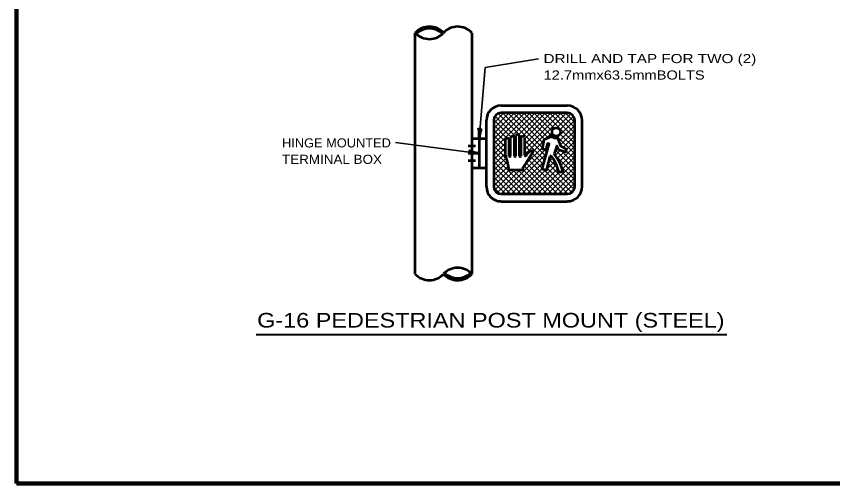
# Model space of a CAD drawing. Extents: x -370 to 486, y -203 to 341.
# Drawn here: x -312.3 to -43.9, y -191.2 to -37.7 of the extents above; entities that cross this region are included whole.
import ezdxf
from ezdxf.enums import TextEntityAlignment as Align

# ---------------------------------------------------------------- set-up
doc = ezdxf.new("R2010")
doc.units = 0
doc.header["$LTSCALE"] = 0.96
doc.header["$PDMODE"] = 32
doc.header["$PDSIZE"] = 0.48
doc.layers.add('1', color=7, linetype='Continuous', lineweight=53)

msp = doc.modelspace()

# ---------------------------------------------------------------- linework, layer by layer
at = {"layer": '1'}
for p, q in [((-181.1461, -122.3035), (-181.1461, -43.0725)), ((-162.5461, -43.0725), (-162.5461, -122.3035)), ((-152.9221, -66.98), (-131.1541, -66.98)), ((-131.1541, -69.38), (-152.9221, -69.38)), ((-157.7461, -93.572), (-157.7461, -71.804)), ((-155.3461, -71.804), (-155.3461, -93.572)), ((-128.7301, -93.572), (-128.7301, -71.804)), ((-126.3061, -93.572), (-126.3061, -71.804)), ((-149.7781, -83.636), (-149.7781, -77.396)), ((-148.6261, -77.396), (-148.6261, -83.636)), ((-148.0741, -83.636), (-148.0741, -76.82)), ((-146.9461, -76.82), (-146.9461, -83.636)), ((-146.3701, -83.636), (-146.3701, -77.396)), ((-145.2421, -77.396), (-145.2421, -83.204)), ((-161.3461, -80.288), (-163.7461, -80.288)), ((-157.7461, -77.888), (-162.5461, -77.888)), ((-160.1461, -77.888), (-160.1461, -87.488)), ((-151.4821, -83.636), (-151.4821, -77.948)), ((-150.3301, -77.948), (-150.3301, -83.636)), ((-142.4821, -82.268), (-145.3381, -86.852)), ((-161.3461, -85.088), (-163.7461, -85.088)), ((-157.7461, -87.488), (-162.5461, -87.488)), ((-132.5701, -88.844), (-133.9381, -88.844)), ((-152.9221, -95.996), (-131.1541, -95.996)), ((-152.9221, -98.42), (-131.1541, -98.42))]:
    msp.add_line(p, q, dxfattribs=at)
at = {"layer": '1', "lineweight": 25}
for p, q in [((-155.3461, -72.74), (-151.9861, -69.38)), ((-155.3461, -74.468), (-150.2581, -69.38)), ((-155.3461, -76.172), (-148.5541, -69.38)), ((-155.3461, -77.876), (-146.8501, -69.38)), ((-155.3461, -79.58), (-145.1221, -69.38)), ((-155.3461, -81.308), (-143.4181, -69.38)), ((-155.1061, -70.82), (-153.9061, -69.596)), ((-146.2501, -77.276), (-153.9301, -69.62)), ((-138.2581, -83.564), (-152.4421, -69.38)), ((-139.2661, -80.852), (-150.7381, -69.38)), ((-149.4661, -77.156), (-141.7141, -69.38)), ((-139.0021, -79.388), (-149.0101, -69.38)), ((-138.6661, -78.044), (-147.3061, -69.38)), ((-147.2101, -76.58), (-140.0101, -69.38)), ((-146.0341, -77.132), (-138.2821, -69.38)), ((-137.4421, -77.54), (-145.6021, -69.38)), ((-145.2421, -78.044), (-136.5781, -69.38)), ((-145.2421, -79.748), (-134.8741, -69.38)), ((-145.2421, -81.452), (-133.1701, -69.38)), ((-145.2421, -83.18), (-131.4421, -69.38)), ((-136.1701, -77.108), (-143.8741, -69.38)), ((-136.1701, -75.404), (-142.1701, -69.38)), ((-135.4501, -74.396), (-140.4661, -69.38)), ((-128.7301, -79.412), (-138.7621, -69.38)), ((-128.7301, -77.708), (-137.0341, -69.38)), ((-128.7301, -75.98), (-135.3301, -69.38)), ((-134.6101, -74.276), (-130.0261, -69.668)), ((-128.7301, -74.276), (-133.6261, -69.38)), ((-128.7301, -72.572), (-131.8981, -69.38)), ((-149.6821, -77.276), (-155.3221, -71.636)), ((-148.0741, -77.18), (-154.8661, -70.388)), ((-134.5381, -77.612), (-128.7301, -71.804)), ((-133.6021, -74.972), (-129.1141, -70.484)), ((-129.1621, -70.412), (-129.7381, -69.86)), ((-151.0021, -77.66), (-155.3461, -73.34)), ((-151.4821, -78.908), (-155.3461, -75.044)), ((-133.9381, -78.716), (-128.7301, -73.508)), ((-151.4821, -80.612), (-155.3461, -76.748)), ((-150.3301, -78.02), (-149.7781, -77.444)), ((-148.6261, -78.02), (-148.0741, -77.444)), ((-146.9461, -78.02), (-146.3701, -77.468)), ((-138.1861, -77.852), (-136.1701, -75.812)), ((-135.9301, -77.3), (-135.4501, -76.82)), ((-128.7301, -82.844), (-134.6101, -76.964)), ((-128.7301, -81.116), (-133.6021, -76.244)), ((-133.4821, -79.964), (-128.7301, -75.212)), ((-132.4741, -80.684), (-128.7301, -76.94)), ((-151.4821, -82.34), (-155.3461, -78.452)), ((-155.3461, -83.012), (-151.4821, -79.148)), ((-151.1941, -84.308), (-155.3461, -80.18)), ((-149.7781, -78.908), (-150.3301, -78.332)), ((-150.3301, -79.724), (-149.7781, -79.148)), ((-149.7781, -80.612), (-150.3301, -80.036)), ((-148.0741, -78.884), (-148.6261, -78.332)), ((-148.6261, -79.724), (-148.0741, -79.172)), ((-148.0741, -80.588), (-148.6261, -80.036)), ((-146.3701, -78.884), (-146.9461, -78.308)), ((-146.9461, -79.748), (-146.3701, -79.172)), ((-146.3701, -80.588), (-146.9461, -80.012)), ((-138.6181, -84.932), (-145.2421, -78.308)), ((-143.2261, -82.028), (-145.2421, -80.012)), ((-142.3861, -82.052), (-138.8581, -78.5)), ((-138.2101, -81.284), (-137.4181, -80.492)), ((-137.5381, -80.876), (-137.9701, -80.42)), ((-137.1781, -79.532), (-137.2261, -79.484)), ((-134.4181, -80.564), (-134.6101, -80.372)), ((-133.8181, -85.436), (-128.7301, -80.348)), ((-132.7141, -80.54), (-133.5781, -79.7)), ((-131.5621, -81.476), (-128.7301, -78.644)), ((-155.3461, -84.716), (-151.4821, -80.852)), ((-150.5221, -86.684), (-155.3461, -81.884)), ((-155.3461, -86.444), (-151.4821, -82.556)), ((-152.9221, -95.996), (-138.4261, -81.476)), ((-151.2181, -95.996), (-138.0661, -82.844)), ((-150.3301, -81.428), (-149.7781, -80.876)), ((-149.7781, -82.316), (-150.3301, -81.74)), ((-150.3301, -83.132), (-149.7781, -82.58)), ((-148.6261, -81.452), (-148.0741, -80.876)), ((-148.0741, -82.316), (-148.6261, -81.74)), ((-148.6261, -83.156), (-148.0741, -82.58)), ((-146.9461, -81.452), (-146.3701, -80.876)), ((-146.3701, -82.292), (-146.9461, -81.74)), ((-146.9461, -83.156), (-146.3701, -82.604)), ((-144.2101, -82.748), (-145.2421, -81.716)), ((-145.0741, -86.42), (-139.2181, -80.588)), ((-138.9781, -86.276), (-142.6741, -82.58)), ((-137.8981, -82.22), (-138.6661, -81.452)), ((-128.7301, -89.684), (-135.4741, -82.94)), ((-135.1861, -83.372), (-133.4821, -81.692)), ((-128.7301, -87.956), (-135.0661, -81.62)), ((-135.0421, -81.548), (-134.3221, -80.828)), ((-134.4421, -84.356), (-132.2341, -82.148)), ((-133.2661, -86.612), (-128.7301, -82.052)), ((-128.7301, -86.252), (-133.1701, -81.812)), ((-128.7301, -84.548), (-131.6101, -81.668)), ((-142.9381, -95.996), (-155.3461, -83.588)), ((-155.3461, -88.148), (-151.2901, -84.092)), ((-144.6421, -95.996), (-155.3461, -85.316)), ((-155.3461, -89.852), (-150.8581, -85.364)), ((-150.0661, -83.732), (-150.3301, -83.468)), ((-149.5141, -95.996), (-138.6901, -85.172)), ((-148.3621, -83.732), (-148.6261, -83.444)), ((-146.6581, -83.732), (-146.9461, -83.444)), ((-134.3701, -95.996), (-144.6421, -85.748)), ((-132.6661, -95.996), (-143.9701, -84.692)), ((-139.3381, -87.62), (-143.3221, -83.636)), ((-139.2421, -95.996), (-128.7301, -85.484)), ((-137.9941, -87.908), (-135.3061, -85.22)), ((-137.3701, -85.58), (-135.9541, -84.164)), ((-134.3221, -87.5), (-137.1301, -84.692)), ((-135.9781, -84.14), (-136.6021, -83.516)), ((-132.8341, -87.884), (-128.7301, -83.78)), ((-155.3461, -91.556), (-150.5221, -86.756)), ((-146.3461, -95.996), (-155.3461, -87.02)), ((-155.3461, -93.284), (-150.2341, -88.172)), ((-155.0581, -94.7), (-148.5061, -88.172)), ((-154.2421, -95.612), (-146.8021, -88.172)), ((-141.2101, -95.996), (-149.0581, -88.172)), ((-147.7861, -95.996), (-139.3141, -87.5)), ((-139.5061, -95.996), (-147.3541, -88.172)), ((-146.0821, -95.996), (-138.3061, -88.22)), ((-137.8021, -95.996), (-145.7941, -88.004)), ((-136.0981, -95.996), (-145.2901, -86.804)), ((-144.3781, -95.996), (-134.7541, -86.372)), ((-142.6741, -95.996), (-134.2741, -87.62)), ((-130.9861, -95.972), (-138.9781, -87.98)), ((-129.7141, -95.516), (-137.8501, -87.38)), ((-137.5381, -95.996), (-128.7301, -87.188)), ((-128.9461, -94.58), (-137.4901, -86.036)), ((-128.7301, -91.388), (-133.1221, -86.996)), ((-148.0741, -95.996), (-155.3461, -88.724)), ((-149.7781, -95.996), (-155.3461, -90.428)), ((-140.9461, -95.996), (-133.8181, -88.844)), ((-135.8101, -95.996), (-128.7301, -88.892)), ((-134.1061, -95.996), (-128.7301, -90.62)), ((-128.7301, -93.092), (-132.9781, -88.844)), ((-151.4821, -95.996), (-155.3461, -92.156)), ((-153.2101, -95.972), (-155.2981, -93.884)), ((-132.4021, -95.996), (-128.7301, -92.324)), ((-130.6261, -95.948), (-128.8021, -94.1))]:
    msp.add_line(p, q, dxfattribs=at)
at = {"layer": '1', "lineweight": 35}
msp.add_line((-160.1461, -82.688), (-187.65, -79.0884), dxfattribs=at)
at = {"layer": '1', "lineweight": 40}
msp.add_line((-233.414, -142.1299), (-78.7574, -142.1299), dxfattribs=at)
at = {"layer": '1', "lineweight": 158}
msp.add_line((479.406, -191.1602), (-312.194, -191.1602), dxfattribs=at)
msp.add_lwpolyline([(479.406, 334.9398), (-312.294, 334.8398), (-312.194, -191.1602)], dxfattribs=at)
at = {"layer": '1', "lineweight": 35}
msp.add_lwpolyline([(-160.1461, -77.888), (-158.1604, -54.4238), (-140.6305, -51.6378)], dxfattribs=at)
at = {"layer": '1'}
for points in [[(-136.8661, -83.66), (-138.0901, -88.292), (-139.3861, -87.812), (-137.1541, -79.484), (-137.7061, -79.388), (-138.2581, -81.524), (-139.3381, -81.332), (-138.7861, -78.068), (-136.2421, -77.06)], [(-134.3461, -77.588), (-133.4101, -80.156), (-131.4901, -81.26), (-131.7781, -82.316), (-134.0821, -81.476), (-134.5621, -80.18), (-135.4981, -82.772)], [(-145.7941, -87.596), (-145.7941, -88.172), (-150.3301, -88.172)]]:
    msp.add_lwpolyline(points, dxfattribs=at)
msp.add_circle((-134.8153, -75.6145), 1.3721, dxfattribs=at)
for centre, radius, start, end in [((-176.4961, -47.3865), 6.3555, 42.97503, 137.02497), ((-176.4961, -48.0533), 6.3555, 47.11243, 132.88757), ((-167.2103, -47.3865), 6.3555, 42.97503, 137.02497), ((-176.4961, -38.7401), 6.3555, 222.97503, 317.02497), ((-152.9185, -71.8067), 4.8384, 90, 180), ((-131.1457, -71.8067), 4.8384, 0, 90), ((-152.9185, -71.8067), 2.4192, 90, 180), ((-131.1457, -71.8067), 2.4192, 0, 90), ((-150.9038, -78.3176), 0.6706, 32.26726, 147.73274), ((-149.2028, -77.7506), 0.6706, 32.26726, 147.73274), ((-147.5018, -77.1836), 0.6706, 32.26726, 147.73274), ((-145.8008, -77.7506), 0.6706, 32.26726, 147.73274), ((-134.8253, -75.6562), 1.9808, 224.78621, 284.15055), ((-144.8821, -83.1081), 0.367, 196.62901, 346.9737), ((-141.8779, -84.7843), 3.0894, 107.58203, 148.94869), ((-142.661, -82.0714), 0.2764, 313.16859, 122.89183), ((-134.681, -82.7521), 0.8157, 180.88666, 241.05185), ((-163.7197, -89.1016), 13.4156, 4.00065, 24.07184), ((-150.0533, -83.2977), 0.4365, 229.49744, 310.50256), ((-148.3523, -83.2977), 0.4365, 229.49744, 310.50256), ((-146.6513, -83.2977), 0.4365, 229.49744, 310.50256), ((-136.1971, -84.5635), 1.1259, 102.87116, 125.96864), ((-147.2214, -91.7593), 13.5959, 12.34164, 37.58932), ((-145.6503, -91.6667), 13.3818, 12.13626, 37.79469), ((-144.6436, -87.7979), 1.1728, 125.78093, 170.21865), ((-152.9185, -93.5795), 4.8384, 180, 270), ((-152.9185, -93.5795), 2.4192, 180, 270), ((-131.1457, -93.5795), 4.8384, 270, 0), ((-131.1457, -93.5795), 2.4192, 270, 0), ((-167.2103, -126.6175), 6.3555, 42.97503, 137.02497), ((-176.4961, -117.9711), 6.3555, 222.97503, 317.02497), ((-167.2103, -117.9711), 6.3555, 222.97503, 317.02497), ((-167.2103, -117.3043), 6.3555, 227.11243, 312.88757)]:
    msp.add_arc(centre, radius, start, end, dxfattribs=at)
at = {"layer": '1', "lineweight": 60}
for centre, major_axis, ratio, start_param, end_param in [((-160.3661, -76.5553), (0.006, -2.151), 0.122415, 0.89635335, 3.14159265), ((-159.7797, -76.5696), (-0.3878, -2.0825), 0.07063, 3.14071475, 5.41810995), ((-161.4875, -82.8468), (2.149, -0.0923), 0.122415, 0.89635335, 3.14159265), ((-161.4464, -82.2617), (2.0626, -0.4825), 0.07063, 3.14071475, 5.41810995)]:
    msp.add_ellipse(centre, major_axis=major_axis, ratio=ratio, start_param=start_param, end_param=end_param, dxfattribs=at)
at = {"layer": '1'}
for p in [(-136.2421, -77.06), (-151.4821, -83.636)]:
    msp.add_point(p, dxfattribs=at)

# ---------------------------------------------------------------- texts
for s, width, p in [('DRILL AND TAP FOR TWO (2)', 1.25, (-138.9647, -53.0215)), ('12.7mmx63.5mmBOLTS', 1.2, (-138.9647, -58.4215)), ('HINGE MOUNTED', 1.05, (-224.951, -80.7154)), ('TERMINAL BOX', 1.1, (-224.951, -86.1154))]:
    msp.add_text(s, height=3, dxfattribs=dict(at, width=width)).set_placement(p)
at = {"layer": '1', "width": 1.2}
msp.add_text('G-16 PEDESTRIAN POST MOUNT (STEEL)', height=4.8, dxfattribs=at).set_placement((-156.2985, -139.8771), align=Align.CENTER)

doc.saveas('drawing.dxf')
